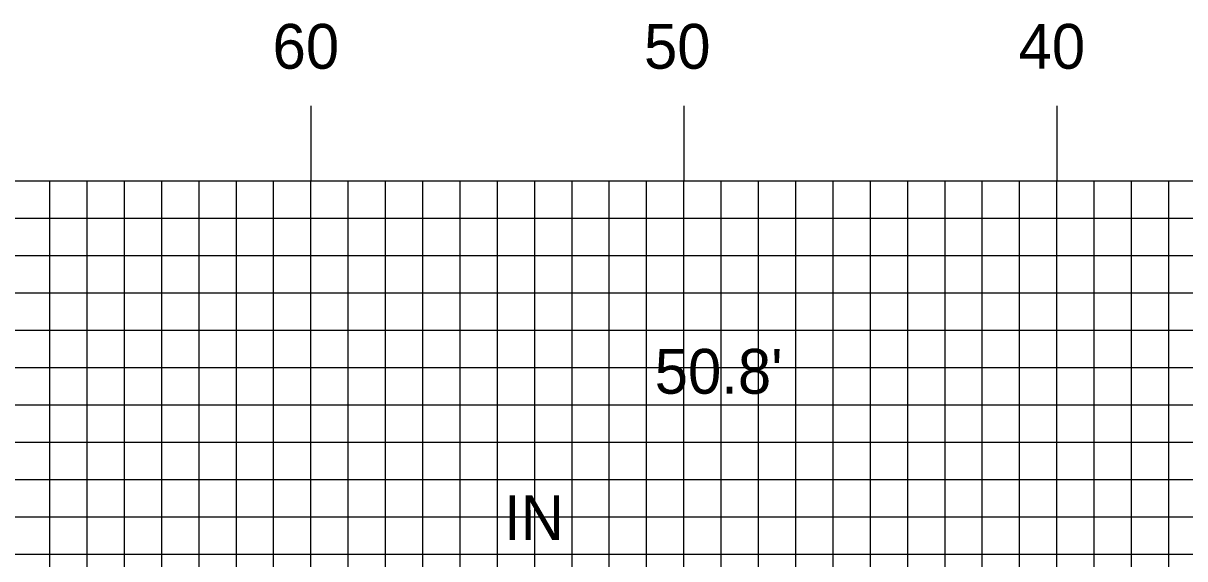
# Model space of a CAD drawing. Extents: x 1819244 to 1819587, y 442591 to 442811.
# Drawn here: x 1819341.95 to 1819373.09, y 442758.54 to 442772.88 of the extents above; entities that cross this region are included whole.
import ezdxf

# ---------------------------------------------------------------- set-up
doc = ezdxf.new("R2010")
doc.units = 0
for name, color, linetype in [('ANNOTATION', 7, 'Continuous'), ('D_Text_Standard', 7, 'Continuous'), ('H_V ANNOTATION', 7, 'Continuous'), ('MAJOR', 7, 'Continuous'), ('MINOR', 7, 'Continuous')]:
    doc.layers.add(name, color=color, linetype=linetype)

msp = doc.modelspace()

# ---------------------------------------------------------------- linework, layer by layer
at = {"layer": 'MAJOR'}
for p, q in [((1819349.665, 442770.669), (1819349.665, 442768.665)), ((1819359.665, 442770.669), (1819359.665, 442768.665)), ((1819369.665, 442770.669), (1819369.665, 442768.665)), ((1819269.665, 442768.665), (1819549.665, 442768.665)), ((1819269.665, 442768.665), (1819549.665, 442768.665)), ((1819349.665, 442743.665), (1819349.665, 442768.665)), ((1819359.665, 442743.665), (1819359.665, 442768.665)), ((1819369.665, 442743.665), (1819369.665, 442768.665)), ((1819269.665, 442763.665), (1819549.665, 442763.665)), ((1819269.665, 442758.665), (1819549.665, 442758.665))]:
    msp.add_line(p, q, dxfattribs=at)
at = {"layer": 'MINOR'}
for p, q in [((1819342.665, 442743.665), (1819342.665, 442768.665)), ((1819343.665, 442743.665), (1819343.665, 442768.665)), ((1819344.665, 442743.665), (1819344.665, 442768.665)), ((1819345.665, 442743.665), (1819345.665, 442768.665)), ((1819346.665, 442743.665), (1819346.665, 442768.665)), ((1819347.665, 442743.665), (1819347.665, 442768.665)), ((1819348.665, 442743.665), (1819348.665, 442768.665)), ((1819350.665, 442743.665), (1819350.665, 442768.665)), ((1819351.665, 442743.665), (1819351.665, 442768.665)), ((1819352.665, 442743.665), (1819352.665, 442768.665)), ((1819353.665, 442743.665), (1819353.665, 442768.665)), ((1819354.665, 442743.665), (1819354.665, 442768.665)), ((1819355.665, 442743.665), (1819355.665, 442768.665)), ((1819356.665, 442743.665), (1819356.665, 442768.665)), ((1819357.665, 442743.665), (1819357.665, 442768.665)), ((1819358.665, 442743.665), (1819358.665, 442768.665)), ((1819360.665, 442743.665), (1819360.665, 442768.665)), ((1819361.665, 442743.665), (1819361.665, 442768.665)), ((1819362.665, 442743.665), (1819362.665, 442768.665)), ((1819363.665, 442743.665), (1819363.665, 442768.665)), ((1819364.665, 442743.665), (1819364.665, 442768.665)), ((1819365.665, 442743.665), (1819365.665, 442768.665)), ((1819366.665, 442743.665), (1819366.665, 442768.665)), ((1819367.665, 442743.665), (1819367.665, 442768.665)), ((1819368.665, 442743.665), (1819368.665, 442768.665)), ((1819370.665, 442743.665), (1819370.665, 442768.665)), ((1819371.665, 442743.665), (1819371.665, 442768.665)), ((1819372.665, 442743.665), (1819372.665, 442768.665)), ((1819269.665, 442767.665), (1819549.665, 442767.665)), ((1819269.665, 442766.665), (1819549.665, 442766.665)), ((1819269.665, 442765.665), (1819549.665, 442765.665)), ((1819269.665, 442764.665), (1819549.665, 442764.665)), ((1819269.665, 442762.665), (1819549.665, 442762.665)), ((1819269.665, 442761.665), (1819549.665, 442761.665)), ((1819269.665, 442760.665), (1819549.665, 442760.665)), ((1819269.665, 442759.665), (1819549.665, 442759.665))]:
    msp.add_line(p, q, dxfattribs=at)

# ---------------------------------------------------------------- texts
at = {"layer": 'ANNOTATION'}
msp.add_text('IN', height=1.2, dxfattribs=at).set_placement((1819354.841, 442759.042))
at = {"layer": 'D_Text_Standard'}
msp.add_text("50.8'", height=1.2, dxfattribs=at).set_placement((1819358.881, 442762.961))
at = {"layer": 'H_V ANNOTATION'}
for s, p in [('60', (1819348.637, 442771.665)), ('50', (1819358.594, 442771.665)), ('40', (1819368.637, 442771.665))]:
    msp.add_text(s, height=1.2, dxfattribs=at).set_placement(p)

doc.saveas('drawing.dxf')
